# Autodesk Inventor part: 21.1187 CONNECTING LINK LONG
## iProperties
Created: 2007-08
Part Number: 21.1187 CONNECTING LINK LONG
Document SubType Name: Modeling
Designer: Andy Moles
Material: Steel
Density: 7.85 g/cm^3
Author: Andy Moles
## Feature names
1. Extrusion1
2. Extrusion2
